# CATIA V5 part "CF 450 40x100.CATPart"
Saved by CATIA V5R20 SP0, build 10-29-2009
Part number: CF 450 40x100
Definition: NONE
Nomenclature: CF 450 40x100
Source: Unknown
Description: CF 450 40x100
Bounding box of the stored display mesh (mm): x -31.5 to 31.5, y 0 to 100, z -31.5 to 31.5
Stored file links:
  C:\Users\Utente\Desktop\IO LAVORO\3D X SITO CF\X SITO\CF 450\CF 450 40x100.CATPart
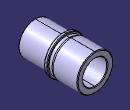
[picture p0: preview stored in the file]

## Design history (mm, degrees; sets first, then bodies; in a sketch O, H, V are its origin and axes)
Body1 "CF 450 40x100" (main body)
  Solid1: solid without history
